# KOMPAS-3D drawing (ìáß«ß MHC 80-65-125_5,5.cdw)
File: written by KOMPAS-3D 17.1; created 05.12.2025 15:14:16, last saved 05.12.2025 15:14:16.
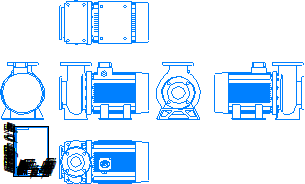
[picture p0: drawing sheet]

Sheet 1: A4, portrait

Title block, sheet 1: name: Насос MHC 80-65-125_5,5 / 5,5 кВт 3х380В; material: Сталь 10  ГОСТ 1050-88; mass: 193,06; sheets: 1; sheet format: A4

Views: Вид 1, Спереди, Проекционный вид 2, Проекционный вид 3, Проекционный вид 4, Проекционный вид 5, Проекционный вид 6
Referenced files in \\adlc.lan\data\АДЛ_ПКД\3D-модели\ADL production\Насосы ГРАНПАМП\Насосы ГРАНПАМП серии МНС\KOMPAS 3D\: Насос МНС 80-65-125_5,5.m3d
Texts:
  Andrey
  АДЛ
Dimensions and other numbers on the sheet: 1:1; 1; 5,5 кВт 3х380В; 193,06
